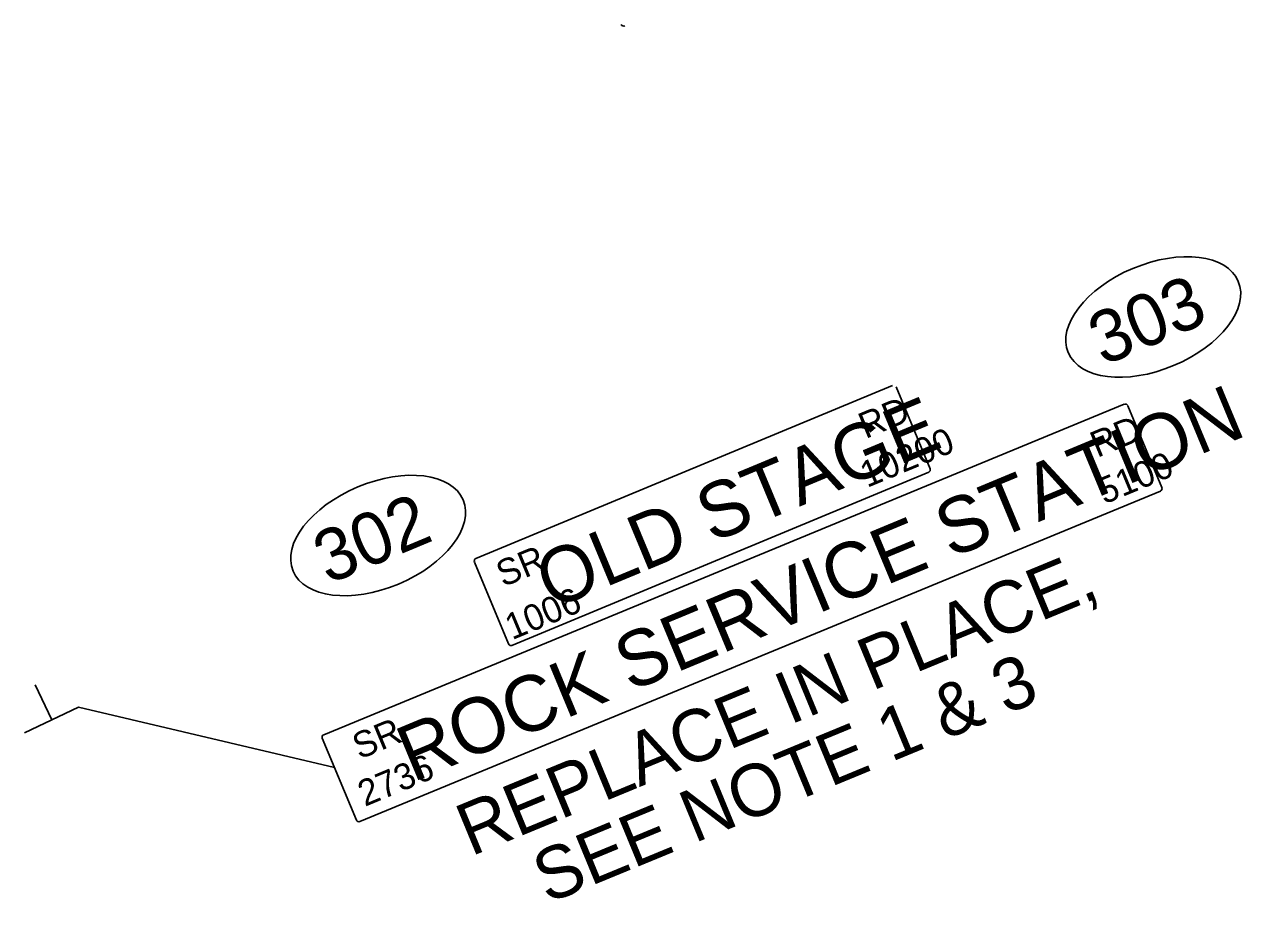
# Model space of a CAD drawing. Extents: x 2096670 to 2098561, y 684033 to 689893.
# Drawn here: x 2098279.4 to 2098561.4, y 685917.9 to 686120 of the extents above; entities that cross this region are included whole.
import ezdxf

# ---------------------------------------------------------------- set-up
doc = ezdxf.new("R2010")
doc.units = 0
for name, color, linetype in [('Exist Sign D', 7, 'Continuous'), ('Prop DSN Text', 7, 'Continuous'), ('Prop Sign E Keep Right CELL', 7, 'Continuous'), ('Prop Sign E One Way_Right CELL', 7, 'Continuous'), ('Prop Sign E Signal Light Ahead CELL', 7, 'Continuous')]:
    doc.layers.add(name, color=color, linetype=linetype)

msp = doc.modelspace()

# ---------------------------------------------------------------- linework, layer by layer
at = {"layer": 'Exist Sign D'}
msp.add_arc((2098417.38, 686120.22), 0.609, 202.5843, 292.5843, dxfattribs=at)
at = {"layer": 'Prop DSN Text'}
for p, q in [((2098285.71, 685959.93), (2098281.89, 685967.99)), ((2098279.44, 685956.96), (2098291.88, 685962.86))]:
    msp.add_line(p, q, dxfattribs=at)
at = {"layer": 'Prop Sign E Keep Right CELL'}
for p, q in [((2098479.28, 686036.92), (2098383.33, 685997.06)), ((2098487.92, 686017.72), (2098480.08, 686036.59)), ((2098532.63, 686032.58), (2098348.33, 685956.52)), ((2098541.28, 686013.38), (2098533.43, 686032.25)), ((2098487.6, 686016.92), (2098391.64, 685977.07)), ((2098540.95, 686012.59), (2098356.64, 685936.52)), ((2098390.85, 685977.4), (2098383, 685996.26)), ((2098355.84, 685936.85), (2098348, 685955.72))]:
    msp.add_line(p, q, dxfattribs=at)
for centre, start, end in [((2098532.87, 686032.02), 22.5843, 112.5843), ((2098487.36, 686017.49), 292.5843, 22.5843), ((2098540.71, 686013.15), 292.5843, 22.5843), ((2098383.56, 685996.5), 112.5843, 202.5843), ((2098391.41, 685977.63), 202.5843, 292.5843), ((2098348.56, 685955.95), 112.5843, 202.5843), ((2098356.41, 685937.09), 202.5843, 292.5843)]:
    msp.add_arc(centre, 0.609, start, end, dxfattribs=at)
at = {"layer": 'Prop Sign E One Way_Right CELL'}
for centre in [(2098539.29, 686052.66), (2098360.85, 686002.36)]:
    msp.add_ellipse(centre, major_axis=(-19.58, -8.19), ratio=0.571429, dxfattribs=at)
at = {"layer": 'Prop Sign E Signal Light Ahead CELL'}
msp.add_line((2098350.81, 685948.96), (2098291.88, 685962.86), dxfattribs=at)

# ---------------------------------------------------------------- texts
at = {"layer": 'Prop DSN Text'}
for s, p in [('REPLACE IN PLACE, ', (2098382.22, 685928.44)), ('SEE NOTE 1 & 3', (2098399.82, 685917.53))]:
    msp.add_text(s, height=12, rotation=22.4258, dxfattribs=at).set_placement(p)
at = {"layer": 'Prop Sign E Keep Right CELL'}
for s, height, p in [('ROCK SERVICE STATION', 12.8025, (2098368.79, 685945.51)), ('OLD STAGE ', 12.803, (2098400.73, 685985.23)), ('RD', 6, (2098473.06, 686024.55)), ('RD', 6, (2098526.41, 686020.21)), ('10200', 6, (2098473.41, 686013.3)), ('5100', 6, (2098528.01, 686009.48)), ('SR', 6, (2098389.64, 685990.44)), ('1006', 6, (2098391.68, 685978.25)), ('SR', 6, (2098356.55, 685950.76)), ('2736', 6, (2098357.79, 685939.89))]:
    msp.add_text(s, height=height, rotation=22.5843, dxfattribs=at).set_placement(p)
at = {"layer": 'Prop Sign E One Way_Right CELL'}
for s, p in [('303', (2098527.74, 686041.35)), ('302', (2098349.33, 685991.06))]:
    msp.add_text(s, height=11.98, rotation=22.6926, dxfattribs=at).set_placement(p)

doc.saveas('drawing.dxf')
